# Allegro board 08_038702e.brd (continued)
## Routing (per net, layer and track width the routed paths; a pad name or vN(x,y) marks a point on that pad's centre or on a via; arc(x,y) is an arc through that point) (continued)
IO_L06_12_JX3_P: length 72.1
  TOP w0.089: U1.AA13 v1(26.22,31.59)
  L7_SIG w0.089: v1(15.5,37.32) 15.55,37.32 15.88,37.66 16.83,37.66 17.03,37.46 17.03,37.01 17.07,36.97 17.07,34.62 17.15,34.54 17.15,34.04 17.43,33.76 18.45,33.76 18.72,34.04 18.72,35.72 18.8,35.8 18.8,36.29 18.72,36.38 18.72,37.63 18.74,37.65 18.74,38.14 18.72,38.15 18.72,38.52 18.8,38.6 18.8,39.09 18.72,39.17 18.72,40.03 19.06,40.37 19.53,40.37 19.86,40.03 19.86,38.56 19.95,38.47 19.95,38.2 19.86,38.11 19.86,36.63 19.78,36.55 19.78,36.06 19.86,35.98 19.86,34.62 19.95,34.54 19.95,34.26 19.86,34.18 19.86,31.95 19.95,31.87 19.95,27.29 20.33,26.91 21.06,26.91 21.08,26.93 21.28,26.93 21.35,27 21.46,27 21.81,27.34 21.81,33.79 22.02,34 22.35,34 22.62,33.73 22.62,33.34 22.66,33.31 22.66,32.87 22.62,32.83 22.62,32.34 22.66,32.31 22.66,31.87 22.62,31.83 22.62,27.29 22.99,26.93 23.35,26.93 23.37,26.91 24.06,26.91 24.08,26.93 24.52,26.93 24.88,27.29 24.88,27.73 25.08,27.93 25.35,27.93 25.36,27.92 26.07,27.92 26.08,27.93 26.35,27.93 26.48,27.8 26.6,27.68 26.6,25.25 26.93,24.92 28.42,24.92 28.88,25.38 28.88,27.73 28.88,27.73 28.88,28.3 28.88,28.3 28.88,28.81 28.5,29.19 28.37,29.19 28.31,29.25 28.08,29.25 27.88,29.45 27.88,30.32 27.48,30.72 26.85,30.72 26.6,30.46 26.6,29.57 26.55,29.53 26.55,29.45 26.35,29.25 26.27,29.25 26.21,29.19 25.26,29.19 25.2,29.25 25.08,29.25 24.88,29.45 24.88,31.73 25.08,31.93 25.52,31.93 25.56,31.96 25.84,31.96 v1(26.22,31.59)
  BOTTOM w0.089: v1(15.5,37.32) 15.33,37.48 14.56,37.48 14.28,37.2 14.28,36.77 13.95,36.43 13.51,36.43 13.26,36.17 JX3.64
IO_L06_13_JX2_N: length 72.2
  TOP w0.089: U1.AB24 v1(25.22,19.59)
  L3_SIG w0.089: v1(25.22,19.59) 25.55,19.92 25.71,19.92 25.82,19.81 25.82,19.55 25.59,19.32 25.59,19.02 25.62,18.98 25.62,17.34 26.1,16.87 27.59,16.87 27.88,17.16 27.88,20.66 27.81,20.73 27.81,20.83 27.46,21.18 27.36,21.18 27.35,21.19 26.14,21.19 25.88,21.45 25.88,28.87 26.01,29 26.42,29 26.55,28.87 26.55,22.33 26.93,21.95 27.5,21.95 27.88,22.33 27.88,22.8 28.08,23 28.35,23 28.55,22.8 28.55,19.51 28.63,19.43 28.63,18.84 28.62,18.83 28.62,15.22 29.01,14.84 36.37,14.84 37.01,14.21 38.15,14.21 38.53,13.82 38.53,12.55 38.03,12.05 38.03,9 38.53,8.49 38.82,8.49 38.9,8.41 39.39,8.41 39.47,8.49 40.97,8.49 41.07,8.39 41.07,7.45 40.84,7.22 38.96,7.22 38.66,6.92 38.66,6.5 38.96,6.2 40.99,6.2 41.22,5.97 41.22,5.66 41,5.44 39.44,5.44 38.68,4.68 38.26,4.68 38.03,4.91 38.03,7.52 38.15,7.65 v1(38.15,7.98)
  BOTTOM w0.089: JX2.20 38.33,7.3 38.03,7.6 38.03,7.86 v1(38.15,7.98)
IO_L06_13_JX2_P: length 72.2
  TOP w0.089: U1.AA24 v1(26.22,19.59)
  L3_SIG w0.089: v1(37.64,7.98) 37.64,7.65 37.57,7.58 37.57,7.47 37.77,7.27 37.77,4.81 38.15,4.43 38.79,4.43 39.55,5.19 41.11,5.19 41.48,5.56 41.48,6.08 41.09,6.46 39.06,6.46 38.91,6.61 38.91,6.82 39.06,6.97 40.95,6.97 41.33,7.35 41.33,8.49 41.07,8.74 39.36,8.74 39.28,8.66 39,8.66 38.92,8.74 38.64,8.74 38.28,9.1 38.28,11.94 38.79,12.45 38.79,13.93 38.26,14.46 37.11,14.46 36.48,15.09 29.11,15.09 28.88,15.33 28.88,18.73 28.88,18.73 28.88,19.54 28.81,19.61 28.81,22.91 28.46,23.25 27.97,23.25 27.62,22.91 27.62,22.44 27.39,22.21 27.04,22.21 26.81,22.44 26.81,28.97 26.53,29.25 25.9,29.25 25.62,28.97 25.62,21.34 26.03,20.94 27.24,20.94 27.26,20.93 27.35,20.93 27.55,20.73 27.55,20.63 27.62,20.56 27.62,17.27 27.48,17.13 26.2,17.13 25.88,17.45 25.88,19.09 25.84,19.13 25.84,19.22 25.84,19.22 26.13,19.5 v1(26.22,19.59)
  BOTTOM w0.089: v1(37.64,7.98) 37.81,7.82 37.81,7.6 37.53,7.32 JX2.18
IO_L06_33_JX1_N: length 73.2
  TOP w0.089: U1.E3 v1(43.22,41.59)
  L7_SIG w0.089: v1(43.22,41.59) 42.85,41.95 42.85,42.7 43.08,42.92 46.39,42.92 46.81,43.34 46.81,43.65 47.2,44.05 47.91,44.05 49.46,45.6 49.46,46.02 49.65,46.21 49.93,46.21 49.94,46.21 50.45,46.21 50.45,46.21 50.73,46.21 50.74,46.21 51.25,46.21 51.25,46.21 51.88,46.21 51.96,46.29 52.24,46.29 52.32,46.21 55.25,46.21 55.25,46.21 55.53,46.21 55.54,46.21 56.05,46.21 56.05,46.21 56.33,46.21 56.34,46.21 58.09,46.21 58.47,45.83 59.72,45.83 60.6,46.72 64.04,46.72 64.44,47.12 64.44,52.15 64.33,52.27 64.33,52.7 64.31,52.72 64.31,52.94 64.95,53.58 64.95,54.82 64.42,55.35 61.63,55.35 61.39,55.59 61.39,59.69 61.63,59.93 65.73,59.93 65.97,59.69 65.97,59.31 66.49,58.78 68.23,58.78 68.76,59.31 68.76,60.81 68.38,61.2 60.38,61.2 60,60.81 60,56.12 59.62,55.73 55.91,55.73 55.68,55.97 55.68,56.62 v1(55.93,56.88)
  BOTTOM w0.089: v1(55.93,56.88) 55.64,56.59 55.64,56.5 55.93,56.21 JX1.63
IO_L06_33_JX1_P: length 73.2
  TOP w0.089: U1.F3 v1(42.22,41.59)
  L7_SIG w0.089: v1(42.22,41.59) 42.6,41.97 42.6,42.81 42.97,43.18 46.28,43.18 46.55,43.45 46.55,43.76 47.1,44.3 47.8,44.3 49.2,45.7 49.2,46.12 49.54,46.46 49.55,46.47 50.04,46.47 50.04,46.46 50.34,46.46 50.35,46.47 50.84,46.47 50.84,46.46 51.14,46.46 51.15,46.47 51.78,46.47 51.85,46.55 52.34,46.55 52.42,46.46 55.14,46.46 55.15,46.47 55.64,46.47 55.64,46.46 55.94,46.46 55.95,46.47 56.44,46.47 56.44,46.46 58.2,46.46 58.58,46.08 59.61,46.08 60.5,46.97 63.93,46.97 64.19,47.23 64.19,52.05 64.07,52.16 64.07,52.6 64.06,52.61 64.06,53.05 64.7,53.68 64.7,54.72 64.31,55.1 61.52,55.1 61.14,55.48 61.14,59.8 61.52,60.18 65.84,60.18 66.22,59.8 66.22,59.42 66.6,59.04 68.12,59.04 68.51,59.42 68.51,60.71 68.27,60.94 60.48,60.94 60.25,60.71 60.25,56.01 59.72,55.48 55.81,55.48 55.42,55.86 55.42,56.62 v1(55.17,56.88)
  BOTTOM w0.089: JX1.61 55.13,56.2 55.42,56.5 55.42,56.62 v1(55.17,56.88)
IO_L06_34_JX4_N: length 73.1
  TOP w0.089: U1.H8 v1(40.22,36.59)
  L4_SIG w0.089: v1(80.19,37.88) 80.52,38.21 80.95,38.21 81.08,38.08 81.08,37.57 81.21,37.45 81.33,37.45 81.46,37.57 81.46,38.08 81.59,38.21 81.84,38.21 81.97,38.08 81.97,37.95 82.03,37.89 82.16,37.89 82.22,37.95 82.22,38.08 82.35,38.21 82.5,38.21 83.51,37.19 84.22,37.19 84.24,37.21 84.52,37.21 84.54,37.19 86.9,37.19 87.43,37.72 87.43,37.85 87.66,38.08 89.23,38.08 89.33,37.98 89.33,37.23 89.26,37.16 89.26,36.61 89.33,36.54 89.33,35.27 89.23,35.16 81.97,35.16 81.44,34.63 81.44,33.89 81.06,33.51 70.43,33.51 70.11,33.19 69.87,33.19 69.68,33 69.51,33 69.32,33.19 69.07,33.19 68.88,33 68.71,33 68.52,33.19 68.27,33.19 68.08,33 67.91,33 67.52,33.39 67.47,33.39 67.1,33.77 67.1,33.82 65.62,35.3 65.62,35.84 65.28,36.17 64.74,36.17 64.74,36.18 63.93,36.18 63.68,36.43 61.63,36.43 60.83,37.23 60.67,37.23 60.62,37.27 60.13,37.27 60.09,37.23 59.22,37.23 58.93,36.94 56.46,36.94 56.33,36.81 54.28,36.81 52.25,34.78 51.77,34.78 51.53,35.01 49.65,35.01 49.33,34.69 48.78,34.69 48.29,35.18 40.04,35.18 39.84,35.38 39.84,36.22 v1(40.22,36.59)
  BOTTOM w0.089: JX4.34 80.88,37.77 80.57,38.08 80.44,38.08 80.24,37.88 v1(80.19,37.88)
IO_L06_34_JX4_P: length 73.1
  TOP w0.089: U1.J8 v1(39.22,36.59)
  L4_SIG w0.089: v1(39.22,36.59) 39.59,36.22 39.59,35.27 39.93,34.92 48.19,34.92 48.68,34.44 49.33,34.44 49.42,34.34 51.58,34.34 51.77,34.53 52.35,34.53 54.38,36.55 56.44,36.55 56.57,36.68 59.03,36.68 59.32,36.98 60.19,36.98 60.24,37.02 60.52,37.02 60.56,36.98 60.72,36.98 61.52,36.18 63.57,36.18 63.83,35.92 64.63,35.92 64.64,35.92 65.18,35.92 65.36,35.73 65.36,35.19 65.7,34.85 65.7,34.37 66.08,33.99 66.12,33.99 66.3,33.82 66.3,33.77 66.88,33.19 66.92,33.19 67.1,33.02 67.1,32.97 67.47,32.59 67.72,32.59 67.87,32.75 68.12,32.75 68.27,32.59 68.52,32.59 68.67,32.75 68.92,32.75 69.07,32.59 69.32,32.59 69.47,32.75 69.72,32.75 69.87,32.59 70.12,32.59 70.3,32.77 70.3,33.01 70.54,33.26 81.17,33.26 81.7,33.78 81.7,34.53 82.08,34.91 89.33,34.91 89.59,35.16 89.59,36.65 89.51,36.72 89.51,37.05 89.59,37.12 89.59,38.08 89.33,38.34 87.56,38.34 87.17,37.95 87.17,37.83 86.79,37.45 84.64,37.45 84.63,37.47 84.14,37.47 84.12,37.45 83.62,37.45 82.6,38.46 v1(80.19,38.46)
  BOTTOM w0.089: JX4.32 80.81,38.57 80.57,38.34 80.32,38.34 v1(80.19,38.46)
IO_L06_35_RX_D5_N: length 39.4
  TOP w0.089: U1.E13 v1(43.22,31.59) ; v6(64.4,32.09) U17.J7
  L15_SIG w0.089: v1(43.22,31.59) 43.2,31.6 42.9,31.6 42.81,31.7 42.81,31.82 42.91,31.92 47.36,31.92 47.44,32 47.46,32 47.81,32.34 47.81,34.11 47.84,34.14 48.71,34.14 48.82,34.04 48.82,32.13 49.22,31.73 49.46,31.73 49.47,31.72 51.14,31.72 51.29,31.57 51.29,29.9 52.13,29.05 53.04,29.05 53.25,28.84 53.25,26.29 54.1,25.45 54.13,25.45 54.14,25.46 54.42,25.46 54.46,25.43 55.91,25.43 55.95,25.39 56.44,25.39 56.78,25.73 56.78,25.78 57.13,26.12 57.24,26.12 57.26,26.14 57.69,26.14 58.09,26.55 58.09,27.18 58.2,27.29 58.62,27.29 58.73,27.18 58.73,26.55 59.13,26.14 59.62,26.14 59.87,26.4 59.87,28.96 60.61,29.7 63.04,29.7 63.54,30.2 63.72,30.2 63.89,30.37 63.89,30.55 64.4,31.05 v6(64.4,32.09)
IO_L06_35_RX_D5_P: length 39.4
  TOP w0.089: v6(63.6,31.29) U17.H8 ; U1.F13 v1(42.22,31.59)
  L15_SIG w0.089: v1(42.22,31.59) 42.81,32.18 47.26,32.18 47.33,32.25 47.35,32.25 47.55,32.45 47.55,34.21 47.74,34.4 48.82,34.4 49.07,34.14 49.07,32.24 49.33,31.99 49.56,31.99 49.57,31.97 51.24,31.97 51.54,31.68 51.54,30.01 52.24,29.31 53.15,29.31 53.51,28.95 53.51,26.4 54.19,25.72 54.53,25.72 54.56,25.68 56.02,25.68 56.05,25.64 56.33,25.64 56.53,25.84 56.53,25.88 57.03,26.38 57.13,26.38 57.15,26.4 57.58,26.4 57.84,26.65 57.84,27.29 58.09,27.54 58.73,27.54 58.98,27.29 58.98,26.65 59.23,26.4 59.51,26.4 59.62,26.5 59.62,29.06 60.5,29.95 62.94,29.95 63.3,30.31 63.3,30.59 63.3,30.59 63.3,30.62 63.47,30.79 63.76,30.79 64.14,31.18 64.14,31.52 64.06,31.6 63.81,31.6 63.68,31.48 63.68,31.38 v6(63.6,31.29)
IO_L07_12_JX3_N: length 72.6
  TOP w0.089: U1.AD10 v1(23.22,34.59)
  L7_SIG w0.089: v1(23.22,34.59) 22.84,34.96 22.84,41.62 22.81,41.65 22.81,41.83 22.46,42.18 21.97,42.18 21.94,42.15 21.49,42.15 21.46,42.18 20.97,42.18 20.94,42.15 19.84,42.15 19.61,42.38 19.61,42.8 19.84,43.03 20.93,43.03 20.97,43 21.46,43 21.5,43.03 21.93,43.03 21.97,43 22.46,43 22.81,43.34 22.81,43.53 22.84,43.56 22.84,44.12 22.53,44.43 19.86,44.43 19.48,44.81 19.48,48.68 19.82,49.01 19.82,49.5 19.47,49.85 19.47,50.8 19.71,51.04 20.32,51.04 20.57,51.29 21.1,51.29 21.12,51.27 21.66,51.27 21.68,51.29 24.06,51.29 24.44,51.67 24.44,52.56 24.06,52.94 23.29,52.94 22.91,53.32 22.91,53.83 22.53,54.21 22.06,54.21 21.66,54.61 21.12,54.61 20.72,54.21 18.24,54.21 17.73,53.7 16.69,53.7 16.31,54.08 16.31,55.2 15.78,55.73 14.81,55.73 14.28,55.2 14.28,52.69 14.66,52.31 17.62,52.31 17.85,52.07 17.85,43.03 17.47,42.65 16.3,42.65 16.02,42.38 15.94,42.38 15.57,42.02 14.91,42.02 14.78,42.15 v3(14.53,42.15)
  L17_SIG w0.089: v3(14.53,42.15) 14.52,42.14 14.39,42.14 14.25,42.27 13.41,42.27 11.74,40.6 10.55,40.6 10.32,40.84 10.19,40.84 10.03,41 v3(9.83,41)
  L19_GND w0.089: v3(9.83,41) 9.7,40.88 v4(9.45,40.88)
  BOTTOM w0.089: v4(9.45,40.88) 9.3,40.73 9.18,40.73 8.94,40.97 JX3.75
IO_L07_12_JX3_P: length 72.5
  TOP w0.089: U1.AE10 v1(22.22,34.59)
  L7_SIG w0.089: v1(22.22,34.59) 22.59,34.96 22.59,41.51 22.55,41.55 22.55,41.73 22.35,41.92 22.08,41.92 22.04,41.89 21.39,41.89 21.35,41.92 21.08,41.92 21.04,41.89 19.74,41.89 19.36,42.27 19.36,42.91 19.74,43.29 21.04,43.29 21.08,43.25 21.35,43.25 21.39,43.29 22.04,43.29 22.08,43.25 22.35,43.25 22.55,43.45 22.55,43.63 22.59,43.67 22.59,44.02 22.43,44.18 19.76,44.18 19.23,44.71 19.23,48.78 19.57,49.12 19.57,49.4 19.37,49.59 19.3,49.59 19.21,49.68 19.21,49.84 19.22,49.85 19.22,50.91 19.6,51.29 20.22,51.29 20.47,51.54 21.2,51.54 21.22,51.52 21.55,51.52 21.57,51.54 23.95,51.54 24.18,51.78 24.18,52.45 23.95,52.69 23.19,52.69 22.66,53.22 22.66,53.72 22.43,53.96 21.95,53.96 21.55,54.36 21.22,54.36 20.82,53.96 18.34,53.96 17.83,53.45 16.58,53.45 16.05,53.98 16.05,55.1 15.67,55.48 14.91,55.48 14.53,55.1 14.53,52.79 14.76,52.56 17.73,52.56 18.11,52.18 18.11,42.93 17.58,42.4 16.4,42.4 16.13,42.13 16.04,42.13 15.8,41.88 15.8,41.64 15.67,41.51 15.55,41.51 15.29,41.76 15.17,41.76 15.09,41.69 v3(14.78,41.69)
  L17_SIG w0.089: v3(14.78,41.69) 14.48,41.69 14.15,42.02 13.51,42.02 11.84,40.35 10.45,40.35 10.26,40.54 10,40.54 v3(9.83,40.37)
  L19_GND w0.089: v4(9.45,40.37) v3(9.83,40.37)
  BOTTOM w0.089: JX3.73 8.87,40.17 9.2,40.49 9.32,40.49 v4(9.45,40.37)
IO_L07_13_JX2_N: length 74
  TOP w0.089: U1.AF22 v1(21.22,21.59)
  L7_SIG w0.089: v1(40.57,12.43) 40.57,13.82 40.69,13.95 41.51,13.95 41.85,13.61 41.85,13.28 41.84,13.26 41.84,12.4 41.86,12.37 41.86,12.09 41.2,11.42 41.2,9.2 41.12,9.12 41.12,8.63 41.2,8.54 41.2,8.26 41.73,7.73 45.77,7.73 46.15,7.35 46.15,5.44 46.53,5.06 47.15,5.06 47.68,5.59 47.68,7.16 47.86,7.35 48.13,7.35 48.31,7.16 48.31,5.59 48.84,5.06 49.84,5.06 50.22,5.44 50.22,6.71 50.98,7.47 50.98,9.87 50.45,10.4 44.73,10.4 44.5,10.63 44.5,12.88 43.01,14.37 42.49,14.37 41.89,14.97 39.19,14.97 38.17,13.95 37.75,13.95 37.37,14.33 31.65,14.33 30.89,15.09 26.19,15.09 25.81,15.48 25.81,22.83 25.46,23.18 21.97,23.18 21.62,22.83 21.62,22.45 21.59,22.41 21.59,21.96 v1(21.22,21.59)
  BOTTOM w0.089: JX2.25 40.73,11.72 40.4,12.05 40.4,12.26 v1(40.57,12.43)
IO_L07_13_JX2_P: length 74
  TOP w0.089: U1.AE22 v1(22.22,21.59)
  L7_SIG w0.089: v1(39.93,12.43) 39.8,12.55 39.68,12.55 39.55,12.68 39.55,12.81 39.68,12.94 40.18,12.94 40.31,13.06 40.31,13.93 40.59,14.21 40.8,14.21 41.62,14.21 42.11,13.71 42.11,13.17 42.09,13.15 42.09,12.5 42.12,12.47 42.12,11.98 41.45,11.32 41.45,9.09 41.37,9.01 41.37,8.73 41.45,8.65 41.45,8.36 41.84,7.98 45.88,7.98 46.41,7.45 46.41,5.55 46.64,5.32 47.04,5.32 47.42,5.7 47.42,7.27 47.76,7.6 48.23,7.6 48.57,7.27 48.57,5.7 48.95,5.32 49.73,5.32 49.96,5.55 49.96,6.82 50.73,7.58 50.73,9.76 50.34,10.14 44.63,10.14 44.25,10.52 44.25,12.77 42.91,14.11 42.38,14.11 41.78,14.71 39.3,14.71 38.28,13.7 37.64,13.7 37.26,14.08 31.55,14.08 30.79,14.84 26.09,14.84 25.55,15.38 25.55,22.73 25.35,22.93 22.08,22.93 21.88,22.73 21.88,22.36 21.84,22.31 21.84,21.96 v1(22.22,21.59)
  BOTTOM w0.089: JX2.23 39.93,11.79 40.18,12.05 40.18,12.17 v1(39.93,12.43)
IO_L07_33_JX1_N: length 72.7
  TOP w0.089: U1.H1 v1(40.22,43.59)
  L14_SIG w0.089: v1(55.81,49.51) 55.68,49.38 55.68,48.47 56.04,48.11 61.8,48.11 62.05,48.37 62.05,48.88 62.3,49.13 63.28,49.13 64.04,48.37 64.46,48.37 65.22,49.13 72.06,49.13 72.44,49.51 73.46,49.51 73.84,49.13 73.84,48.51 73.46,48.13 72.7,48.13 72.04,47.48 71.48,47.48 71.47,47.5 71.13,47.5 71.11,47.48 65.33,47.48 65.08,47.23 65.08,47.07 64.99,46.98 64.99,46.76 64.82,46.59 63.04,46.59 62.66,46.21 62.66,45.57 62.62,45.53 62.62,45.46 62.27,45.11 61.78,45.11 61.7,45.19 61.65,45.19 61.27,45.57 61.27,46.21 60.89,46.59 59.62,46.59 59.23,46.21 59.23,45.45 58.85,45.07 58.09,45.07 57.71,45.45 57.71,46.21 57.33,46.59 55.55,46.59 54.79,47.35 54.79,48.39 54.54,48.64 54.54,49.74 55.06,50.27 55.45,50.27 55.68,50.51 55.68,50.68 55.45,50.91 48.04,50.91 47.1,49.98 47.03,49.98 46.83,49.78 46.83,49.7 44.65,47.52 44.65,47.46 44.27,47.08 44.21,47.08 43.21,46.08 41.05,46.08 40.44,45.47 40.44,44.83 39.84,44.24 39.84,43.96 v1(40.22,43.59)
  BOTTOM w0.089: JX1.64 55.93,50.31 55.64,50.02 55.64,49.68 v1(55.81,49.51)
IO_L07_33_JX1_P: length 72.7
  TOP w0.089: U1.J1 v1(39.22,43.59)
  L14_SIG w0.089: v1(55.26,49.48) 55.42,49.32 55.42,48.37 55.93,47.86 61.9,47.86 62.3,48.26 62.3,48.77 62.41,48.88 63.17,48.88 63.93,48.11 64.57,48.11 65.33,48.88 72.17,48.88 72.55,49.26 73.35,49.26 73.59,49.03 73.59,48.62 73.35,48.39 72.59,48.39 71.94,47.73 71.59,47.73 71.57,47.75 71.03,47.75 71.01,47.73 65.22,47.73 64.82,47.33 64.82,47.17 64.74,47.09 64.74,46.87 64.72,46.84 62.94,46.84 62.41,46.31 62.41,45.68 62.36,45.63 62.36,45.56 62.17,45.37 61.89,45.37 61.81,45.45 61.75,45.45 61.52,45.68 61.52,46.31 60.99,46.84 59.51,46.84 58.98,46.31 58.98,45.55 58.75,45.32 58.2,45.32 57.96,45.55 57.96,46.31 57.43,46.84 55.66,46.84 55.04,47.46 55.04,48.5 54.79,48.75 54.79,49.64 55.17,50.02 55.55,50.02 55.93,50.4 55.93,50.78 55.55,51.16 47.93,51.16 47,50.23 46.92,50.23 46.58,49.88 46.58,49.81 44.39,47.63 44.39,47.57 44.16,47.33 44.1,47.33 43.11,46.34 40.95,46.34 40.18,45.57 40.18,44.94 39.59,44.34 39.59,43.96 v1(39.22,43.59)
  BOTTOM w0.089: JX1.62 55.13,50.22 55.39,49.96 55.39,49.62 v1(55.26,49.48)
IO_L07_34_JX4_N: length 72.4
  TOP w0.089: U1.E5 v1(43.22,39.59)
  L17_SIG w0.089: v1(84.38,36.24) 84.32,36.24 84.19,36.11 84.06,36.11 83.87,36.3 83.87,36.35 83.95,36.43 83.95,36.56 83.88,36.62 83.47,36.62 81.17,38.93 78.45,38.93 73.33,44.05 73.33,49.64 72.7,50.27 71.17,50.27 70.79,49.89 70.79,47.48 70.41,47.1 68.63,47.1 68.25,47.48 68.25,49.89 67.87,50.27 65.33,50.27 63.25,48.2 59.96,48.2 59.96,48.19 59.47,48.19 59.46,48.2 55.76,48.2 54.79,47.23 54.79,44.81 54.41,44.43 53.14,44.43 52.76,44.81 52.76,47.82 52.38,48.2 51.63,48.2 49.46,46.02 49.46,45.76 47.88,44.18 43.11,44.18 42.85,43.92 42.85,40.06 42.84,40.05 42.84,39.96 v1(43.22,39.59)
  BOTTOM w0.089: v1(84.38,36.24) 84.55,36.41 84.76,36.41 85,36.17 JX4.37
IO_L07_34_JX4_P: length 72.4
  TOP w0.089: U1.F5 v1(42.22,39.59)
  L17_SIG w0.089: v1(84.38,36.88) 83.58,36.88 81.27,39.18 78.56,39.18 73.59,44.16 73.59,49.74 72.8,50.53 71.07,50.53 70.54,50 70.54,47.58 70.3,47.35 68.74,47.35 68.51,47.58 68.51,50 67.98,50.53 65.22,50.53 63.15,48.45 59.86,48.45 59.85,48.44 59.57,48.44 59.57,48.45 55.66,48.45 54.54,47.33 54.54,44.92 54.3,44.69 53.24,44.69 53.01,44.92 53.01,47.92 52.48,48.45 51.53,48.45 49.2,46.12 49.2,45.86 47.77,44.43 43,44.43 42.6,44.03 42.6,40.17 42.59,40.16 42.59,39.96 v1(42.22,39.59)
  BOTTOM w0.089: v1(84.38,36.88) 84.63,36.62 84.76,36.62 85.11,36.97 JX4.35
IO_L07_35_RX_FRAME_N: length 35.9
  TOP w0.089: U1.H12 v1(40.22,32.59) ; v6(64.4,30.49) U17.G7
  L17_SIG w0.089: v6(64.4,30.49) 64.18,30.49 64.13,30.54 64.13,30.76 64.05,30.84 63.89,31 63.47,31 63.3,31.17 63.3,31.5 63,31.79 62.59,31.79 62.3,31.5 62.3,31.17 62.12,30.99 60.23,30.99 59.58,31.64 58.49,31.64 58.05,32.09 54.44,32.09 54.42,32.07 53.93,32.07 53.69,31.83 53.69,31.48 53.57,31.35 52.61,31.35 52.53,31.43 52.53,32.37 52.27,32.62 51.79,32.62 51.39,32.22 51.39,31.58 51.28,31.48 50.83,31.48 50.73,31.58 50.73,32.37 50.47,32.62 49.88,32.62 49.48,32.22 49.48,31.51 49.4,31.43 49.32,31.43 49.32,31.43 49.2,31.43 48.95,31.69 48.95,32.22 48.54,32.62 47.83,32.62 47.58,32.37 47.58,31.48 47.55,31.45 47.55,31.3 47.5,31.25 47.35,31.25 47.32,31.22 46.89,31.22 46.81,31.31 46.81,31.83 46.46,32.18 46.42,32.18 46.39,32.22 45.03,32.22 45,32.18 44.97,32.18 44.63,31.83 44.63,31.32 44.52,31.22 43.85,31.22 43.81,31.26 43.81,31.83 43.46,32.18 43.37,32.18 43.34,32.22 40.59,32.22 v1(40.22,32.59)
IO_L07_35_RX_FRAME_P: length 36.1
  TOP w0.089: U1.H13 v1(40.22,31.59) ; v6(63.6,30.49) U17.G8
  L17_SIG w0.089: v1(40.22,31.59) 40.59,31.96 43.23,31.96 43.27,31.92 43.35,31.92 43.55,31.73 43.55,31.16 43.74,30.97 44.63,30.97 44.88,31.22 44.88,31.73 45.08,31.92 45.1,31.92 45.14,31.96 46.28,31.96 46.32,31.92 46.35,31.92 46.55,31.73 46.55,31.21 46.79,30.97 47.43,30.97 47.46,31 47.6,31 47.81,31.2 47.81,31.35 47.83,31.37 47.83,32.26 47.94,32.37 48.44,32.37 48.69,32.11 48.69,31.58 49.1,31.18 49.21,31.18 49.22,31.18 49.59,31.18 49.73,31.33 49.73,32.11 49.99,32.37 50.37,32.37 50.47,32.26 50.47,31.48 50.73,31.22 51.39,31.22 51.64,31.48 51.64,32.11 51.89,32.37 52.17,32.37 52.27,32.26 52.27,31.33 52.5,31.1 53.67,31.1 53.95,31.37 53.95,31.8 54.01,31.87 54.51,31.87 54.52,31.88 57.96,31.88 58.41,31.44 59.49,31.44 60.14,30.79 62.2,30.79 62.5,31.09 62.5,31.42 62.67,31.59 62.92,31.59 63.1,31.42 63.1,31.09 63.39,30.79 63.45,30.79 63.45,30.79 63.74,30.79 63.87,30.66 63.87,30.44 63.93,30.36 63.93,30.28 63.86,30.23 63.76,30.23 63.68,30.31 63.68,30.41 v6(63.6,30.49)
IO_L08_12_JX3_N: length 72.8
  TOP w0.089: U1.AF12 v1(21.22,32.59)
  L15_SIG w0.089: v3(14.02,41) 13.28,41 12.75,40.47 12.75,38.44 12.52,38.21 8.96,38.21 8.43,37.68 8.43,37.04 8.79,36.68 9.45,36.68 9.96,36.18 9.96,35.75 10.34,35.37 14.92,35.37 15.01,35.29 15.52,35.29 15.63,35.4 15.69,35.4 17.32,37.03 17.32,39.48 15.8,41 15.8,42.04 16.56,42.8 16.56,51.95 16.79,52.18 17.6,52.18 17.83,51.95 17.83,40.77 18.85,39.75 18.85,34.25 18.62,34.02 16.08,34.02 15.55,33.49 15.55,31.35 15.93,30.97 19.99,30.97 20.37,31.35 20.37,33.51 20.79,33.93 21.35,33.93 21.59,33.69 21.59,32.96 v1(21.22,32.59)
  L19_GND w0.089: v4(13.36,40.97) 13.99,40.97 v3(14.02,41)
  BOTTOM w0.089: JX3.76 v4(13.36,40.97)
IO_L08_12_JX3_P: length 72.8
  TOP w0.089: U1.AE12 v1(22.22,32.59)
  L15_SIG w0.089: v1(22.22,32.59) 21.84,32.96 21.84,33.8 21.46,34.18 20.68,34.18 20.12,33.61 20.12,31.46 19.89,31.22 16.03,31.22 15.8,31.46 15.8,33.38 16.18,33.76 18.72,33.76 19.1,34.14 19.1,39.86 18.09,40.88 18.09,52.05 17.71,52.43 16.69,52.43 16.31,52.05 16.31,42.91 15.55,42.15 15.55,40.9 17.07,39.37 17.07,37.13 15.59,35.65 15.53,35.65 15.42,35.54 15.11,35.54 15.03,35.62 10.44,35.62 10.21,35.86 10.21,36.28 9.56,36.94 8.9,36.94 8.69,37.15 8.69,37.57 9.07,37.95 12.63,37.95 13.01,38.34 13.01,40.37 13.39,40.75 13.46,40.75 13.54,40.67 13.67,40.67 13.74,40.75 13.8,40.75 13.88,40.67 13.89,40.67 13.9,40.66 13.9,40.49 13.95,40.44 v3(14.02,40.44)
  L19_GND w0.089: v4(13.39,40.24) 13.82,40.24 v3(14.02,40.44)
  BOTTOM w0.089: v4(13.39,40.24) 13.32,40.17 JX3.74
IO_L08_13_JX2_N: length 73.9
  TOP w0.089: U1.AF23 v1(21.22,20.59)
  L7_SIG w0.089: v1(21.22,20.59) 21.61,20.59 21.64,20.56 21.64,20.41 21.41,20.18 20.65,20.18 20.25,19.77 20.25,13.47 22.81,10.9 24.58,10.9 25.2,10.29 25.2,6.48 26.49,5.19 27.52,5.19 27.6,5.27 27.67,5.27 28.99,6.59 35.13,6.59 35.87,5.85 35.87,3.69 36.27,3.28 36.63,3.28 36.88,3.03 36.88,1.76 37.14,1.51 53.52,1.51 53.9,1.89 53.9,3.16 53.52,3.54 46,3.54 45.77,3.77 45.77,4.1 45.85,4.18 45.85,5.44 45.47,5.82 40.73,5.82 40.5,6.06 40.5,7.92 v1(40.57,7.98)
  BOTTOM w0.089: v1(40.57,7.98) 40.44,7.86 40.44,7.6 40.73,7.31 JX2.26
IO_L08_13_JX2_P: length 74
  TOP w0.089: U1.AE23 v1(22.22,20.59)
  L7_SIG w0.089: v1(22.22,20.59) 22.18,20.56 21.99,20.56 21.9,20.47 21.9,20.3 21.52,19.93 20.76,19.93 20.5,19.67 20.5,13.57 22.91,11.16 24.69,11.16 25.45,10.4 25.45,6.59 26.6,5.44 27.41,5.44 27.49,5.52 27.57,5.52 28.88,6.84 35.23,6.84 36.12,5.95 36.12,3.79 36.37,3.54 36.73,3.54 37.14,3.13 37.14,1.86 37.24,1.76 53.41,1.76 53.65,1.99 53.65,3.05 53.41,3.28 45.9,3.28 45.52,3.66 45.52,4.2 45.6,4.29 45.6,5.34 45.37,5.57 40.63,5.57 40.25,5.95 40.25,6.9 40.06,7.09 39.73,7.09 39.63,7.2 39.63,7.37 39.73,7.47 40.12,7.47 40.25,7.6 40.25,7.79 v1(40.06,7.98)
  BOTTOM w0.089: v1(40.06,7.98) 40.22,7.82 40.22,7.6 39.93,7.31 JX2.24
IO_L08_33_JX1_N: length 73.5
  TOP w0.089: U1.H3 v1(40.22,41.59)
  L15_SIG w0.089: v1(40.22,41.59) 40.55,41.25 43.5,41.25 43.61,41.36 43.61,44.07 43.36,44.33 43.36,45.55 43.76,45.96 47.19,45.96 47.53,46.3 47.53,47.24 47.91,47.63 49.64,47.63 50.16,47.1 50.34,47.1 51.87,48.62 55.4,48.62 55.78,48.24 64.59,48.24 64.82,48.47 64.82,49.91 64.59,50.15 55.45,50.15 54.92,50.68 54.92,51.27 55.19,51.54 65.48,51.54 65.71,51.78 65.71,52.45 65.48,52.69 65.04,52.69 64.89,52.83 64.56,52.83 64.42,52.69 62.86,52.69 62.48,52.31 61.03,52.31 60.53,52.81 56.33,52.81 55.81,53.34 55.81,54.74 56.17,55.1 57.39,55.1 57.84,54.65 57.84,54.3 57.93,54.21 57.97,54.21 v1(58.22,53.96)
  BOTTOM w0.089: v1(58.22,53.96) 58.22,54.09 58.07,54.23 58.07,54.36 58.33,54.61 JX1.69
IO_L08_33_JX1_P: length 73.4
  TOP w0.089: U1.H4 v1(40.22,40.59)
  L15_SIG w0.089: v1(40.22,40.59) 40.62,41 43.61,41 43.87,41.26 43.87,44.18 43.61,44.43 43.61,45.45 43.87,45.7 47.3,45.7 47.79,46.19 47.79,47.14 48.02,47.37 49.53,47.37 50.06,46.84 50.45,46.84 51.97,48.37 55.3,48.37 55.68,47.99 64.7,47.99 65.08,48.37 65.08,50.02 64.7,50.4 55.55,50.4 55.17,50.78 55.17,51.16 55.3,51.29 65.58,51.29 65.97,51.67 65.97,52.56 65.58,52.94 65.14,52.94 65,53.09 64.46,53.09 64.31,52.94 62.76,52.94 62.38,52.56 61.14,52.56 60.63,53.07 56.44,53.07 56.06,53.45 56.06,54.63 56.27,54.85 56.54,54.85 56.75,54.64 56.75,54.54 56.82,54.46 56.95,54.46 57.08,54.59 57.08,54.72 57.2,54.85 57.29,54.85 57.59,54.55 v1(57.59,53.96)
  BOTTOM w0.089: v1(57.59,53.96) 57.59,53.96 57.84,54.21 57.84,54.34 57.53,54.65 JX1.67
IO_L08_34_JX4_N: length 73.5
  TOP w0.089: U1.D8 v1(44.22,36.59)
  L4_SIG w0.089: v1(80.19,36.34) 80.17,36.36 80.17,36.54 80.23,36.6 80.33,36.6 80.41,36.68 80.83,36.68 80.94,36.58 80.94,36.43 80.82,36.31 80.7,36.31 80.57,36.18 80.57,35.92 80.7,35.8 80.82,35.8 80.94,35.68 80.94,35.41 80.81,35.29 79.81,35.29 79.68,35.41 79.68,38.08 79.3,38.46 78.67,38.46 78.28,38.08 78.28,34.5 78.05,34.27 77.25,34.27 77.01,34.5 77.01,37.55 76.48,38.08 75.36,38.08 74.98,37.7 74.98,34.63 74.75,34.4 74.2,34.4 73.97,34.63 73.97,37.55 73.44,38.08 72.34,38.08 71.81,37.55 71.81,34.5 71.57,34.27 70.9,34.27 70.66,34.5 70.66,37.55 70.13,38.08 69.67,38.08 69.14,37.55 69.14,34.88 68.91,34.65 68.48,34.65 68.25,34.88 68.25,37.55 67.72,38.08 66.44,38.08 66.19,37.83 66.19,37.57 65.93,37.32 63.43,37.32 63.3,37.45 62.66,37.45 62.54,37.32 61.65,37.32 61.01,37.95 57.71,37.95 57.33,38.34 54.68,38.34 54.04,37.69 53.41,37.69 52.61,36.9 52.61,36.66 52.38,36.43 51.84,36.43 51.58,36.68 49.6,36.68 49.35,36.43 47.95,36.43 47.7,36.18 44.97,36.18 44.97,36.18 44.63,36.18 v1(44.22,36.59)
  BOTTOM w0.089: JX4.38 80.83,36.17 80.47,36.53 80.38,36.53 v1(80.19,36.34)
IO_L08_34_JX4_P: length 73.5
  TOP w0.089: U1.D9 v1(44.22,35.59)
  L4_SIG w0.089: v1(80.19,36.94) 80.94,36.94 81.19,36.68 81.19,35.29 80.94,35.03 79.68,35.03 79.43,35.29 79.43,37.98 79.19,38.21 78.77,38.21 78.54,37.98 78.54,34.4 78.16,34.02 77.14,34.02 76.76,34.4 76.76,37.45 76.38,37.83 75.47,37.83 75.24,37.6 75.24,34.53 74.86,34.14 74.09,34.14 73.71,34.53 73.71,37.45 73.33,37.83 72.44,37.83 72.06,37.45 72.06,34.4 71.68,34.02 70.79,34.02 70.41,34.4 70.41,37.45 70.03,37.83 69.78,37.83 69.39,37.45 69.39,34.78 69.01,34.4 68.38,34.4 68,34.78 68,37.45 67.62,37.83 66.55,37.83 66.44,37.72 66.44,37.47 66.04,37.07 63.32,37.07 63.19,37.19 62.77,37.19 62.64,37.07 61.54,37.07 60.91,37.7 57.6,37.7 57.22,38.08 54.79,38.08 54.15,37.44 53.51,37.44 52.86,36.79 52.86,36.56 52.48,36.18 51.77,36.18 51.53,35.94 49.65,35.94 49.42,36.18 48.06,36.18 47.81,35.92 45.08,35.92 45.07,35.92 44.55,35.92 v1(44.22,35.59)
  BOTTOM w0.089: v1(80.19,36.94) 80.38,36.75 80.51,36.75 80.73,36.97 JX4.36
IO_L08_35_FB_CLK_N: length 39.2
  TOP w0.089: v6(62,30.49) U17.G10 ; U1.J13 v1(39.22,31.59)
  L17_SIG w0.089: v6(62,30.49) 62.28,30.21 62.28,29.95 62.16,29.83 60.12,29.83 59.74,29.45 58.2,29.45 57.74,29.9 57.11,29.9 56.8,30.21 56.23,30.21 55.92,30.51 55.43,30.51 55.21,30.29 54.61,30.29 54.53,30.38 53.72,30.38 53.55,30.21 34.96,30.21 34.72,30.44 34.72,31.75 34.96,31.99 37.39,31.99 37.64,31.73 37.64,30.86 37.92,30.59 38.49,30.59 38.84,30.94 38.84,31.32 38.7,31.46 38.57,31.59 38.57,31.79 38.74,31.96 39.12,31.96 39.22,31.86 39.22,31.59 v1(39.22,31.59)
IO_L08_35_FB_CLK_P: length 38
  TOP w0.089: U1.K13 v1(38.22,31.59) ; v6(62,28.89) U17.F10
  L17_SIG w0.089: v1(38.22,31.59) 38.59,31.22 38.59,31.05 38.39,30.84 38.03,30.84 37.9,30.97 37.9,31.84 37.5,32.24 34.85,32.24 34.47,31.86 34.47,30.33 34.85,29.95 53.66,29.95 53.83,30.12 54.42,30.12 54.51,30.04 55.32,30.04 55.54,30.26 55.82,30.26 56.12,29.95 56.69,29.95 57,29.65 57.64,29.65 58.09,29.19 59.85,29.19 60.23,29.57 61.77,29.57 62.03,29.32 62.03,28.92 v6(62,28.89)
IO_L09_12_JX3_N: length 72.7
  TOP w0.089: U1.AF10 v1(21.22,34.59)
  L17_SIG w0.089: v3(7.29,43.16) 7.55,42.91 8.16,42.91 8.56,42.5 8.56,39.88 7.93,39.25 7.93,26.38 8.41,25.89 9.2,25.89 9.45,26.14 9.45,27.16 9.96,27.67 11.33,27.67 11.86,28.2 11.86,37.19 12.24,37.57 13.9,37.57 14.28,37.19 14.28,34 14.38,33.89 16.92,33.89 17.32,33.49 17.32,31.07 17.71,30.69 17.71,26.42 17.18,25.89 16.03,25.89 15.8,25.66 15.8,24.47 16.03,24.24 17.18,24.24 17.71,23.71 17.71,23.21 18.08,22.84 18.6,22.84 18.98,23.21 18.98,29.8 20.12,30.95 20.12,32.67 20.88,33.43 20.88,33.73 21.08,33.93 21.37,33.93 21.5,34.05 21.5,34.13 21.64,34.27 21.64,34.4 21.52,34.53 21.28,34.53 v1(21.22,34.59)
  L19_GND w0.089: v4(6.66,43.16) v3(7.29,43.16)
  BOTTOM w0.089: v4(6.66,43.16) 6.78,43.03 7.04,43.03 7.37,43.37 JX3.81
IO_L09_12_JX3_P: length 72.7
  TOP w0.089: U1.AE11 v1(22.22,33.59)
  L17_SIG w0.089: v1(22.22,33.59) 21.87,33.94 21.74,33.94 21.74,33.94 21.68,33.87 21.55,33.75 21.55,33.45 21.35,33.25 21.06,33.25 20.37,32.57 20.37,30.84 19.23,29.7 19.23,23.11 18.71,22.59 17.97,22.59 17.45,23.11 17.45,23.6 17.07,23.98 15.93,23.98 15.55,24.37 15.55,25.76 15.93,26.14 17.07,26.14 17.45,26.52 17.45,30.59 17.07,30.97 17.07,33.38 16.82,33.64 14.28,33.64 14.02,33.89 14.02,37.09 13.79,37.32 12.35,37.32 12.12,37.09 12.12,28.09 11.44,27.41 10.06,27.41 9.7,27.05 9.7,26.04 9.3,25.64 8.31,25.64 7.67,26.27 7.67,39.35 8.31,39.99 8.31,42.4 8.05,42.65 7.42,42.65 v3(7.29,42.53)
  L19_GND w0.089: v3(7.29,42.53) 7.29,42.56 7.2,42.65 v4(6.66,42.65)
  BOTTOM w0.089: JX3.79 7.28,42.57 7.04,42.82 6.82,42.82 v4(6.66,42.65)
IO_L09_13_JX2_N: length 72.2
  TOP w0.089: U1.AB22 v1(25.22,21.59)
  L4_SIG w0.089: v1(25.22,21.59) 25.59,21.96 26.46,21.96 26.6,21.83 26.6,16.26 27,15.86 28.14,15.86 28.25,15.75 28.25,14.74 28.65,14.33 29.24,14.33 29.64,14.74 29.64,15.5 29.75,15.6 30.41,15.6 30.66,15.86 30.66,17 30.88,17.22 30.88,26.73 31.08,26.92 33.35,26.92 33.55,26.73 33.55,26.7 33.6,26.65 33.6,24.33 33.81,24.13 33.81,22.08 33.96,21.93 33.96,19.89 33.71,19.64 33.71,18.64 34.47,17.88 34.47,13.7 34.85,13.32 35.1,13.32 35.49,12.94 35.49,12.55 36.56,11.48 36.58,11.48 36.65,11.41 37.26,11.41 37.64,11.03 37.64,10.27 37.9,10.01 43.77,10.01 43.79,10.03 46.66,10.03 46.92,10.28 46.92,10.65 46.66,10.9 38.89,10.9 38.79,11.01 38.79,11.31 38.89,11.41 42.45,11.41 42.89,11.85 42.89,12.21 v1(43.11,12.43)
  BOTTOM w0.089: v1(43.11,12.43) 42.83,12.15 42.83,12.03 43.13,11.73 JX2.31
IO_L09_13_JX2_P: length 72.3
  TOP w0.089: U1.AB21 v1(25.22,22.59)
  L4_SIG w0.089: v1(25.22,22.59) 25.07,22.44 25.07,22.21 25.21,22.07 25.34,22.07 25.48,22.22 26.56,22.22 26.85,21.93 26.85,16.36 27.1,16.11 28.25,16.11 28.5,15.86 28.5,14.84 28.75,14.59 29.14,14.59 29.39,14.84 29.39,15.6 29.64,15.86 30.3,15.86 30.41,15.96 30.41,17.1 30.63,17.32 30.63,26.83 30.97,27.18 33.46,27.18 33.81,26.83 33.81,26.8 33.85,26.76 33.85,24.44 34.06,24.23 34.06,22.19 34.22,22.03 34.22,19.79 33.96,19.53 33.96,18.75 34.72,17.99 34.72,13.8 34.96,13.57 35.21,13.57 35.74,13.04 35.74,12.66 36.66,11.73 36.69,11.73 36.76,11.67 37.37,11.67 37.9,11.14 37.9,10.37 38,10.27 43.67,10.27 43.68,10.28 46.56,10.28 46.66,10.39 46.66,10.54 46.56,10.65 38.79,10.65 38.53,10.9 38.53,11.41 38.79,11.67 42.34,11.67 42.64,11.96 42.64,12.28 42.62,12.3 42.6,12.3 v1(42.47,12.43)
  BOTTOM w0.089: v1(42.47,12.43) 42.6,12.3 42.6,12.05 42.33,11.78 JX2.29
IO_L09_33_JX1_N: length 72.1
  TOP w0.089: U1.K1 v1(38.22,43.59)
  L14_SIG w0.089: v1(58.22,49) 57.91,49.31 57.91,49.38 58.09,49.56 58.09,49.64 57.91,49.82 57.91,49.84 58.35,50.27 76.1,50.27 77.07,51.24 78.03,51.24 78.28,51.49 78.28,52.31 78.03,52.56 76.02,52.56 75.38,51.92 61.77,51.92 61.39,52.31 61.39,52.56 61.01,52.94 59.62,52.94 59.23,52.56 59.23,52.31 58.85,51.92 46.03,51.92 42.49,48.39 42.2,48.39 41.82,48 41.82,47.71 41.33,47.23 40.18,47.23 38.53,45.57 38.53,43.91 v1(38.22,43.59)
  BOTTOM w0.089: v1(58.22,49) 58.03,49.19 58.03,49.96 58.33,50.26 JX1.70
IO_L09_33_JX1_P: length 72.1
  TOP w0.089: U1.K2 v1(38.22,42.59)
  L14_SIG w0.089: v1(57.66,48.96) 57.66,49.95 58.24,50.53 76,50.53 76.96,51.49 77.92,51.49 78.03,51.6 78.03,52.2 77.92,52.31 76.13,52.31 75.49,51.67 61.67,51.67 61.14,52.2 61.14,52.45 60.91,52.69 59.72,52.69 59.49,52.45 59.49,52.2 58.96,51.67 46.13,51.67 42.59,48.13 42.3,48.13 42.07,47.9 42.07,47.61 41.43,46.97 40.29,46.97 38.79,45.47 38.79,43.16 v1(38.22,42.59)
  BOTTOM w0.089: v1(57.66,48.96) 57.75,49.05 57.75,49.08 57.81,49.14 57.81,49.96 57.53,50.24 JX1.68
IO_L09_34_JX4_N: length 72.3
  TOP w0.089: U1.E8 v1(43.22,36.59)
  L17_SIG w0.089: v1(84.38,33.89) 84.19,34.08 84.19,34.18 84.1,34.27 83.87,34.27 83.75,34.14 83.75,34.01 83.63,33.89 83.36,33.89 83.24,34.02 83.24,34.14 83.11,34.27 82.69,34.27 81.21,35.75 79.94,35.75 79.39,36.3 77.42,36.3 71.96,41.76 67.38,41.76 66.85,42.29 66.85,43.9 67.38,44.43 70.56,44.43 70.79,44.66 70.79,45.34 70.56,45.57 67.38,45.57 66.85,46.1 66.85,46.99 66.62,47.23 64.01,47.23 63.68,46.9 63.68,45.34 63.15,44.81 61.5,44.81 61.27,44.58 61.27,43.25 61.27,43.25 61.27,43.03 61.26,43.03 61.26,42.88 60.91,42.53 60.89,42.53 60.88,42.52 59.11,42.52 58.97,42.65 56.89,42.65 56.78,42.54 54.47,42.54 53.72,43.29 52.73,43.29 52.52,43.08 49.59,43.08 49.38,43.29 47.75,43.29 47.46,43 44.15,43 43.88,42.73 43.88,39.34 43.46,38.92 42.08,38.92 41.99,38.84 41.91,38.84 41.82,38.75 41.82,37.19 42.08,36.92 42.35,36.92 42.72,36.56 43.18,36.56 v1(43.22,36.59)
  BOTTOM w0.089: v1(84.38,33.89) 84.55,34.06 84.89,34.06 85.17,33.77 JX4.43
IO_L09_34_JX4_P: length 72.4
  TOP w0.089: U1.F9 v1(42.22,35.59)
  L17_SIG w0.089: v1(84.38,34.53) 82.79,34.53 81.31,36 80.05,36 79.5,36.56 77.52,36.56 72.06,42.02 67.49,42.02 67.11,42.4 67.11,43.8 67.49,44.18 70.66,44.18 71.05,44.56 71.05,45.45 70.66,45.83 67.49,45.83 67.11,46.21 67.11,47.1 66.73,47.48 63.9,47.48 63.43,47 63.43,45.45 63.04,45.07 61.39,45.07 61.01,44.69 61.01,43.14 61.01,43.13 61.01,42.98 60.81,42.79 60.79,42.79 60.77,42.77 59.21,42.77 59.08,42.91 56.79,42.91 56.68,42.8 54.57,42.8 53.83,43.54 52.73,43.54 52.45,43.81 49.65,43.81 49.38,43.54 47.65,43.54 47.35,43.25 44.04,43.25 43.62,42.83 43.62,39.45 43.35,39.18 41.97,39.18 41.89,39.1 41.8,39.1 41.56,38.86 41.56,37.08 41.84,36.81 41.84,36.43 42.22,36.05 42.22,35.59 v1(42.22,35.59)
  BOTTOM w0.089: JX4.41 85.19,34.57 84.89,34.27 84.63,34.27 v1(84.38,34.53)
IO_L09_35_TX_FRAME_N: length 31.6
  TOP w0.089: U1.J15 v1(39.22,28.59) ; v6(62.8,31.29) U17.H9
  L6_SIG w0.089: v1(39.22,28.59) 38.81,28.61 38.74,28.53 38.74,28.43 38.81,28.35 38.81,27.5 39.05,27.25 39.35,27.25 39.63,27.52 39.63,27.83 39.97,28.18 40.28,28.18 40.55,28.45 40.55,28.9 40.56,28.92 40.57,28.93 40.57,29.72 40.62,29.78 40.62,29.83 40.97,30.18 41.02,30.18 41.09,30.25 42.35,30.25 42.62,30.52 42.63,30.62 42.85,30.84 43.49,30.84 43.74,30.59 43.74,30.51 43.99,30.25 51.55,30.25 51.93,30.63 53.71,30.63 53.96,30.38 54.53,30.38 54.57,30.33 55.15,30.33 55.45,30.63 57.65,30.63 58.49,31.48 59.43,31.48 59.82,31.09 59.82,31 60.04,30.79 62.87,30.79 63.04,30.97 63.04,31.13 62.96,31.22 62.87,31.22 v6(62.8,31.29)
IO_L09_35_TX_FRAME_P: length 31.3
  TOP w0.089: U1.K15 v1(38.22,28.59) ; v6(62.8,30.49) U17.G9
  L6_SIG w0.089: v6(62.8,30.49) 62.79,30.49 62.79,30.33 62.54,30.08 62.28,30.08 62.17,30.19 60.27,30.19 59.57,30.9 59.57,30.98 59.33,31.22 58.6,31.22 57.75,30.38 55.55,30.38 55.25,30.08 54.46,30.08 54.42,30.12 53.86,30.12 53.6,30.38 52.04,30.38 51.66,30 43.89,30 43.49,30.4 43.49,30.48 43.38,30.59 42.96,30.59 42.88,30.51 42.88,30.45 42.85,30.4 42.85,30.4 42.84,30.39 42.82,30.36 42.46,30 41.2,30 41.13,29.93 41.08,29.93 40.88,29.73 40.88,29.68 40.82,29.62 40.82,28.92 40.81,28.34 40.39,27.92 40.08,27.92 39.88,27.73 39.88,27.42 39.46,27 38.95,27 38.55,27.39 38.55,28.25 38.24,28.59 v1(38.22,28.59)
IO_L10_12_JX3_N: length 72.5
  TOP w0.089: U1.AF13 v1(21.22,31.59)
  L15_SIG w0.089: v1(14.66,43.8) 14.47,43.61 14.34,43.61 14.28,43.67 14.28,44.05 14.4,44.18 14.66,44.18 14.91,44.43 14.91,44.69 14.78,44.81 14.78,45.02 14.91,45.15 14.91,45.6 14.5,46 14.24,46 13.91,46.34 13.15,46.34 12.63,46.87 12.63,49.28 12.39,49.51 9.73,49.51 9.2,50.04 9.2,50.3 8.96,50.53 7.78,50.53 7.55,50.3 7.55,46.31 7.78,46.08 11.33,46.08 11.86,45.55 11.86,40.39 11.33,39.86 10.19,39.86 10.09,39.75 9.58,39.75 9.47,39.86 7.9,39.86 7.67,39.63 7.67,34 7.9,33.76 13.01,33.76 13.39,33.38 13.39,32.75 13.01,32.37 9.8,32.37 9.72,32.45 9.44,32.45 9.36,32.37 7.65,32.37 7.42,32.13 7.42,30.97 8.31,30.08 14.49,30.08 14.66,30.25 21.35,30.25 21.59,30.49 21.59,31.32 21.82,31.55 21.82,31.93 21.69,32.06 21.46,32.06 21.26,31.86 21.26,31.63 v1(21.22,31.59)
  BOTTOM w0.089: v1(14.66,43.8) 14.53,43.8 13.9,43.16 13.51,43.16 13.3,43.37 JX3.82
IO_L10_12_JX3_P: length 72.5
  TOP w0.089: U1.AE13 v1(22.22,31.59)
  L15_SIG w0.089: v1(14.7,43.25) 14.77,43.33 14.78,43.33 14.98,43.52 14.98,43.65 14.99,43.66 14.99,43.82 15.04,43.87 15.04,44.2 15.17,44.33 15.17,45.7 14.61,46.26 14.35,46.26 14.01,46.59 13.26,46.59 12.88,46.97 12.88,49.38 12.5,49.77 9.83,49.77 9.45,50.15 9.45,50.4 9.07,50.78 7.67,50.78 7.29,50.4 7.29,46.21 7.67,45.83 11.23,45.83 11.61,45.45 11.61,40.49 11.23,40.11 10.09,40.11 9.98,40.01 9.68,40.01 9.57,40.11 7.8,40.11 7.42,39.73 7.42,33.89 7.8,33.51 12.9,33.51 13.13,33.28 13.13,32.85 12.9,32.62 9.9,32.62 9.82,32.7 9.33,32.7 9.25,32.62 7.55,32.62 7.16,32.24 7.16,30.86 8.2,29.83 14.59,29.83 14.76,30 21.46,30 21.84,30.38 21.84,31.22 22.01,31.39 v1(22.22,31.59)
  BOTTOM w0.089: v1(14.7,43.25) 14.66,43.25 14.62,43.29 14.33,43.29 13.95,42.91 13.64,42.91 13.31,42.57 JX3.80
IO_L10_13_JX2_N: length 74.3
  TOP w0.089: U1.AA23 v1(26.22,20.59)
  L6_SIG w0.089: v1(42.98,8.74) 42.72,8.49 42.72,8.36 42.85,8.24 43.23,8.24 43.36,8.11 43.36,7.86 43.23,7.73 42.72,7.73 42.6,7.6 42.6,3.26 43,2.86 47.03,2.86 47.12,2.78 52.56,2.78 52.91,3.12 52.91,3.16 53.16,3.41 56.08,3.41 56.72,4.05 57.86,4.05 58.47,4.66 58.47,8.47 58.6,8.6 58.6,10.14 58.22,10.52 57.48,10.52 56.95,11.05 56.95,13.59 55.57,14.97 52.14,14.97 51.89,15.22 50.88,15.22 50.63,14.97 47.66,14.97 47.02,14.33 40.38,14.33 40.05,14 39.56,14 39.22,14.33 38.85,14.33 38.77,14.25 37.4,14.25 37.32,14.33 36.14,14.33 34.62,15.86 29.16,15.86 28.55,16.46 28.55,20.73 28.32,20.96 26.49,20.96 26.39,20.86 26.39,20.77 v1(26.22,20.59)
  BOTTOM w0.089: v1(42.98,8.74) 42.81,8.58 42.81,7.62 43.13,7.3 JX2.32
IO_L10_13_JX2_P: length 74.4
  TOP w0.089: U1.AA22 v1(26.22,21.59)
  L6_SIG w0.089: v1(26.22,21.59) 26.59,21.22 28.42,21.22 28.81,20.83 28.81,16.57 29.26,16.11 34.72,16.11 36.25,14.59 37.42,14.59 37.5,14.5 38.66,14.5 38.74,14.59 39.33,14.59 39.66,14.25 39.94,14.25 40.28,14.59 46.92,14.59 47.55,15.22 50.52,15.22 50.78,15.48 52,15.48 52.25,15.22 55.68,15.22 57.2,13.7 57.2,11.16 57.58,10.78 58.32,10.78 58.85,10.25 58.85,8.49 58.73,8.36 58.73,4.55 57.96,3.79 56.82,3.79 56.19,3.16 53.27,3.16 53.16,3.05 53.16,3 53.14,2.98 53.13,2.98 52.66,2.52 47.01,2.52 46.93,2.6 42.9,2.6 42.34,3.16 v1(42.34,8.74)
  BOTTOM w0.089: JX2.30 42.33,7.33 42.6,7.6 42.6,8.49 v1(42.34,8.74)
IO_L10_33_JX1_N: length 72.2
  TOP w0.089: U1.G1 v1(41.22,43.59)
  L15_SIG w0.089: v1(41.22,43.59) 40.87,43.24 40.87,43.12 41.06,42.92 41.35,42.92 41.58,42.7 41.58,42.53 41.86,42.25 42.35,42.25 42.55,42.45 42.55,42.46 42.6,42.5 42.6,43.82 41.71,44.71 41.71,46.57 42.24,47.1 45.67,47.1 45.9,47.33 45.9,48.14 45.67,48.37 44.45,48.37 44.24,48.16 43.75,48.16 43.4,48.5 43.4,48.99 43.61,49.2 43.61,50.38 44.02,50.78 53.92,50.78 54.15,51.01 54.15,56.12 54.54,56.5 62.28,56.5 62.54,56.75 62.54,58.27 62.79,58.53 64.57,58.53 64.95,58.15 64.95,56.88 65.33,56.5 66.47,56.5 66.85,56.88 66.85,58.27 67.24,58.66 69.01,58.66 69.39,58.27 69.39,56.88 69.78,56.5 70.82,56.5 71.17,56.14 71.17,55.64 70.82,55.29 60.95,55.29 60.63,54.97 60.63,54.08 v1(60.76,53.96)
  BOTTOM w0.089: JX1.75 60.73,54.6 60.48,54.36 60.48,54.23 v1(60.76,53.96)
IO_L10_33_JX1_P: length 72.2
  TOP w0.089: U1.H2 v1(40.22,42.59)
  L15_SIG w0.089: v1(40.22,42.59) 40.31,42.68 40.31,42.91 40.39,42.98 40.64,42.98 40.88,42.75 40.88,42.45 41.08,42.25 41.5,42.25 41.75,42 42.46,42 42.81,42.34 42.81,42.35 42.85,42.4 42.85,43.93 41.97,44.81 41.97,46.46 42.35,46.84 45.77,46.84 46.15,47.23 46.15,48.24 45.77,48.62 44.34,48.62 44.13,48.41 43.85,48.41 43.66,48.61 43.66,48.89 43.87,49.1 43.87,50.27 44.12,50.53 54.03,50.53 54.41,50.91 54.41,56.01 54.64,56.24 62.39,56.24 62.79,56.65 62.79,58.17 62.9,58.27 64.46,58.27 64.7,58.04 64.7,56.77 65.22,56.24 66.58,56.24 67.11,56.77 67.11,58.17 67.34,58.4 68.91,58.4 69.14,58.17 69.14,56.77 69.67,56.24 70.71,56.24 70.92,56.04 70.92,55.75 70.71,55.54 61.05,55.54 60.84,55.54 60.38,55.08 60.38,54.21 v1(60.12,53.96)
  BOTTOM w0.089: JX1.73 59.93,54.66 60.25,54.34 60.25,54.08 v1(60.12,53.96)
IO_L10_34_JX4_N: length 73.5
  TOP w0.089: U1.D5 v1(44.22,39.59)
  L17_SIG w0.089: v1(80.19,33.89) 79.38,33.89 79.25,33.76 79.25,33.46 79.33,33.38 81.08,33.38 81.21,33.26 81.21,23.2 80.97,22.97 78.82,22.97 78.59,23.2 78.59,33.56 78.21,33.94 77.7,33.94 76.5,35.14 75.96,35.14 72.89,38.21 67.59,38.21 67.21,38.59 67.21,39.73 66.83,40.11 66.09,40.11 65.71,40.49 65.71,43.39 65.18,43.92 63.57,43.92 63.04,43.39 63.04,42.17 63.13,42.09 63.13,41.63 62.66,41.16 62.66,40.49 62.28,40.11 58.85,40.11 58.34,39.61 47.83,39.61 47.44,39.22 44.5,39.22 44.22,39.51 v1(44.22,39.59)
  BOTTOM w0.089: JX4.44 80.79,33.77 80.49,34.07 80.37,34.07 v1(80.19,33.89)
IO_L10_34_JX4_P: length 73.6
  TOP w0.089: U1.E6 v1(43.22,38.59)
  L17_SIG w0.089: v1(80.19,34.53) 80.7,34.02 80.7,33.76 80.82,33.64 81.18,33.64 81.46,33.36 81.46,23.1 81.08,22.71 78.72,22.71 78.34,23.1 78.34,33.46 78.1,33.69 77.6,33.69 76.4,34.89 75.85,34.89 72.79,37.95 67.49,37.95 66.96,38.48 66.96,39.63 66.73,39.86 65.99,39.86 65.46,40.39 65.46,43.29 65.08,43.67 63.68,43.67 63.3,43.29 63.3,42.27 63.38,42.19 63.38,41.52 62.92,41.06 62.92,40.39 62.39,39.86 58.96,39.86 58.45,39.35 47.93,39.35 47.55,38.97 43.81,38.97 43.55,38.71 43.34,38.71 v1(43.22,38.59)
  BOTTOM w0.089: JX4.42 80.74,34.57 80.51,34.33 80.38,34.33 v1(80.19,34.53)
IO_L10_35_EN_AGC: length 28.9
  TOP w0.14: U1.G16 v1(41.22,27.59) ; v6(66.8,30.49) U17.G5
  L6_SIG w0.095: v6(66.8,30.49) 66.76,30.49 65.46,29.19 64.44,29.19 63.81,28.56 59.23,28.56 58.96,28.29 58.96,28.28 58.52,27.84 56.95,27.84 56.83,27.95 56.83,27.95 56.63,28.15 56.63,28.18 56.53,28.27 56.53,28.39 56.33,28.59 56.05,28.59 56.02,28.56 55.57,28.56 55.53,28.59 55.25,28.59 55.05,28.39 55.05,28.34 54.75,28.04 54.75,28.03 54.55,27.84 54.27,27.84 54.18,27.93 44.07,27.93 44.07,27.92 43.36,27.92 43.36,27.93 41.56,27.93 v1(41.22,27.59)
IO_L10_35_SYNC_IN: length 40
  TOP w0.14: U1.G15 v1(41.22,28.59) ; v6(66.8,31.29) U17.H5
  L14_SIG w0.095: v6(66.8,31.29) 67.11,31.6 67.11,32.1 67.4,32.39 67.72,32.39 67.9,32.22 67.9,32.21 68.1,32.01 68.1,31.97 68.27,31.79 68.32,31.79 68.51,31.59 68.52,31.59 68.7,31.42 68.7,31.17 68.63,31.1 68.63,30.68 68.7,30.62 68.7,30.37 68.63,30.3 68.63,29.08 68.7,29.02 68.7,28.77 68.63,28.7 68.63,28.28 68.7,28.22 68.7,27.97 68.63,27.9 68.63,27.48 68.7,27.42 68.7,27.17 68.52,26.99 68.46,26.99 68.38,26.91 65.97,26.91 65.88,26.99 65.87,26.99 65.7,27.17 65.7,27.18 65.5,27.37 65.5,27.42 65.32,27.59 65.07,27.59 65.02,27.54 64.58,27.54 64.52,27.59 64.27,27.59 64.22,27.54 63.78,27.54 63.72,27.59 63.47,27.59 63.42,27.54 62.98,27.54 62.92,27.59 62.67,27.59 62.62,27.54 62.18,27.54 62.12,27.59 61.87,27.59 61.82,27.54 61.38,27.54 61.32,27.59 59.94,27.59 59.17,28.37 58.64,28.37 58.61,28.34 58.33,28.34 58.13,28.54 58.13,29.28 57.17,30.24 55.84,30.24 55.82,30.26 55.54,30.26 55.34,30.06 55.34,29.87 54.15,28.68 49.2,28.68 48.82,29.06 41.71,29.06 41.23,28.59 v1(41.22,28.59)
  BOTTOM w0.14: R111.2 66.79,31.3 v6(66.8,31.29)
IO_L11_35_ENABLE: length 28
  TOP w0.14: v6(66,30.49) U17.G6 ; U1.G14 v1(41.22,29.59)
  L6_SIG w0.095: v6(66,30.49) 65.36,30.49 64.44,29.57 64.06,29.57 63.68,29.19 63.47,29.19 63.47,29.19 62.93,29.19 62.92,29.19 62.67,29.19 62.67,29.19 62.13,29.19 62.12,29.19 61.87,29.19 61.87,29.19 61.33,29.19 61.32,29.19 61.07,29.19 61.07,29.19 60.53,29.19 60.52,29.19 60.27,29.19 60.27,29.19 57.96,29.19 57.58,28.81 56.43,28.81 56.43,28.81 55.96,28.81 55.96,28.81 55.63,28.81 55.62,28.81 55.16,28.81 55.16,28.81 51.57,28.81 51.53,28.78 51.25,28.78 51.22,28.81 50.77,28.81 50.73,28.78 50.45,28.78 50.42,28.81 48.57,28.81 47.93,28.18 42.15,28.18 41.88,28.45 41.88,28.52 41.71,28.68 41.71,29.1 v1(41.22,29.59)
IO_L11_35_TXNRX: length 28.3
  TOP w0.14: U1.F14 v1(42.22,29.59) ; v6(67.6,31.29) U17.H4
  L6_SIG w0.095: v1(42.22,29.59) 42.61,29.19 49.39,29.19 49.65,29.45 51.53,29.45 51.8,29.19 54.93,29.19 55.25,29.52 56.33,29.52 56.58,29.27 56.94,29.27 57.32,29.65 57.52,29.65 57.52,29.65 57.6,29.65 57.8,29.45 63.43,29.45 63.8,29.83 64.31,29.83 65.33,30.84 67.11,30.84 67.56,31.29 v6(67.6,31.29)
IO_L11_SRCC_12_JX3_N: length 72.1
  TOP w0.089: U1.AD11 v1(23.22,33.59)
  L15_SIG w0.089: v1(23.22,33.59) 23.47,33.59 23.56,33.49 23.56,33.12 23.37,32.93 23.08,32.93 22.88,32.73 22.88,32.32 22.55,32 22.55,31.45 22.53,31.43 22.53,29.75 22.55,29.73 22.55,29.45 22.35,29.25 22.21,29.25 22.15,29.19 20.37,29.19 19.74,28.56 18.09,28.56 17.71,28.94 17.71,29.19 17.32,29.57 15.17,29.57 14.78,29.19 10.72,29.19 10.34,28.81 10.34,28.05 9.45,27.16 8.05,27.16 7.29,27.92 7.29,28.79 6.25,29.83 5.51,29.83 5.26,30.08 5.26,32.11 5.01,32.37 1.38,32.37 1.2,32.55 1.2,32.82 1.38,33 5.39,33 5.64,33.26 5.64,33.89 5.39,34.14 1.43,34.14 1.2,34.38 1.2,35.56 1.43,35.8 6.58,35.8 6.91,36.13 6.91,36.6 6.58,36.94 2.06,36.94 1.83,37.17 1.83,37.85 2.06,38.08 4.6,38.08 5.13,38.61 5.13,39.35 6.66,40.88 6.66,43.29 7.16,43.8 7.16,45.19 6.66,45.7 6.66,45.83 v1(6.28,46.21)
  BOTTOM w0.089: JX3.87 7.36,45.77 7.04,45.45 6.78,45.45 6.28,45.96 v1(6.28,46.21)
IO_L11_SRCC_12_JX3_P: length 72.1
  TOP w0.089: U1.AC12 v1(24.22,32.59)
  L15_SIG w0.089: v1(6.02,45.7) 6.2,45.52 6.48,45.52 6.91,45.09 6.91,43.9 6.4,43.39 6.4,40.98 4.88,39.46 4.88,38.72 4.5,38.34 1.96,38.34 1.58,37.95 1.58,37.07 1.96,36.68 6.47,36.68 6.66,36.5 6.66,36.24 6.47,36.05 1.32,36.05 0.94,35.67 0.94,34.27 1.32,33.89 5.28,33.89 5.39,33.79 5.39,33.36 5.28,33.26 1.28,33.26 0.94,32.92 0.94,32.45 1.28,32.11 4.9,32.11 5.01,32.01 5.01,29.98 5.41,29.57 6.15,29.57 7.04,28.68 7.04,27.82 7.95,26.91 9.56,26.91 10.59,27.94 10.59,28.71 10.83,28.94 14.89,28.94 15.27,29.32 17.22,29.32 17.45,29.09 17.45,28.83 17.98,28.3 19.84,28.3 20.48,28.94 22.26,28.94 22.32,29 22.46,29 22.81,29.34 22.81,29.83 22.79,29.85 22.79,31.32 22.81,31.34 22.81,31.89 23.17,32.25 23.35,32.25 23.55,32.45 23.55,32.75 23.74,32.94 23.87,32.94 v1(24.22,32.59)
  BOTTOM w0.089: JX3.85 7.3,44.97 7.04,45.23 6.69,45.23 6.22,45.7 v1(6.02,45.7)
IO_L11_SRCC_13_JX2_N: length 74.3
  TOP w0.089: U1.AD24 v1(23.22,19.59)
  L14_SIG w0.089: v1(45.39,12.43) 45.26,12.3 45.26,10.75 45.5,10.52 46.68,10.52 47.44,11.28 47.91,11.28 48.44,10.75 48.44,9.99 48.67,9.76 49.1,9.76 49.33,9.99 49.33,10.75 49.86,11.28 50.73,11.28 51.11,10.9 51.11,7.75 50.58,7.22 41.96,7.22 40.69,8.49 40.33,8.49 39.93,8.89 39.93,9.66 39.57,10.01 38.38,10.01 37.62,9.25 34.85,9.25 34.34,9.76 34.34,10.18 34.69,10.52 37.26,10.52 37.9,11.16 40.18,11.16 40.82,10.52 43.89,10.52 44.12,10.75 44.12,11.31 43.89,11.54 39.06,11.54 38.53,12.07 38.53,14.08 38.41,14.21 31.42,14.21 30.79,14.84 25.85,14.84 25.07,15.62 25.07,16.49 24.55,17.01 24.55,19.73 24.35,19.93 24.01,19.93 23.94,19.96 23.59,19.96 v1(23.22,19.59)
  BOTTOM w0.089: JX2.37 45.53,11.78 45.26,12.05 45.26,12.3 v1(45.39,12.43)
IO_L11_SRCC_13_JX2_P: length 74.3
  TOP w0.089: U1.AD23 v1(23.22,20.59)
  L14_SIG w0.089: v1(23.22,20.59) 23.17,20.54 23.17,20.26 23.28,20.14 23.41,20.14 23.48,20.22 23.55,20.22 23.63,20.3 23.8,20.3 23.89,20.22 24.01,20.22 24.08,20.18 24.46,20.18 24.81,19.83 24.81,17.12 25.33,16.6 25.33,15.73 25.96,15.09 30.89,15.09 31.53,14.46 38.51,14.46 38.79,14.18 38.79,12.17 39.17,11.79 43.99,11.79 44.38,11.41 44.38,10.86 44.38,10.81 44.38,10.81 44.38,10.65 43.99,10.27 40.71,10.27 40.08,10.9 38,10.9 37.37,10.27 34.79,10.27 34.6,10.07 34.6,9.87 34.96,9.51 37.52,9.51 38.28,10.27 39.68,10.27 40.18,9.76 40.18,9 40.44,8.74 40.8,8.74 42.07,7.47 50.47,7.47 50.85,7.86 50.85,10.8 50.62,11.03 49.96,11.03 49.58,10.65 49.58,9.89 49.2,9.51 48.57,9.51 48.19,9.89 48.19,10.65 47.8,11.03 47.55,11.03 46.79,10.27 45.39,10.27 45.01,10.65 45.01,12.3 v1(44.88,12.43)
  BOTTOM w0.089: JX2.35 44.73,11.76 45.01,12.05 45.01,12.3 v1(44.88,12.43)
IO_L11_SRCC_33_JX1_N: length 72.2
  TOP w0.089: U1.K3 v1(38.22,41.59)
  L4_SIG w0.089: v1(38.22,41.59) 37.84,41.96 37.84,43.74 38.28,44.18 46.03,44.18 46.53,44.69 46.53,45.89 48.89,48.24 54.01,48.24 54.13,48.37 54.94,48.37 55.06,48.24 58.09,48.24 58.49,47.84 58.5,47.84 58.71,47.63 58.71,47.33 58.47,47.09 58.47,46.57 59,46.04 65.21,46.04 65.25,46 65.79,46 65.83,46.04 76.48,46.04 77.01,46.57 77.01,48.6 76.48,49.13 74.09,49.13 73.71,49.51 73.71,49.64 73.33,50.02 72.32,50.02 71.77,49.47 71.77,49.4 71.1,48.73 71.1,47.84 70.87,47.61 68.38,47.61 68,47.99 68,48.24 67.62,48.62 65.99,48.62 65.61,48.24 65.61,47.86 65.22,47.48 65.05,47.48 64.29,48.24 60.85,48.24 60.48,48.61 60.48,49.36 v1(60.63,49.51)
  BOTTOM w0.089: v1(60.63,49.51) 60.38,49.76 60.38,49.89 60.73,50.24 JX1.76
IO_L11_SRCC_33_JX1_P: length 72.1
  TOP w0.089: U1.L3 v1(37.22,41.59)
  L4_SIG w0.089: v1(60.02,49.51) 60.22,49.31 60.22,48.51 60.74,47.99 64.19,47.99 64.95,47.23 65.33,47.23 65.86,47.76 65.86,48.14 66.09,48.37 67.51,48.37 67.74,48.14 67.74,47.88 68.27,47.35 70.97,47.35 71.35,47.73 71.35,48.62 72.02,49.29 72.02,49.37 72.42,49.77 73.23,49.77 73.46,49.53 73.46,49.41 73.99,48.88 76.38,48.88 76.76,48.5 76.76,46.67 76.38,46.29 65.72,46.29 65.69,46.25 65.35,46.25 65.32,46.29 59.11,46.29 58.73,46.67 58.73,46.99 58.96,47.22 58.96,47.73 58.6,48.1 58.6,48.1 58.2,48.5 55.17,48.5 55.04,48.62 54.03,48.62 53.9,48.5 48.78,48.5 46.28,45.99 46.28,44.79 45.92,44.43 38.17,44.43 37.59,43.85 37.59,41.96 v1(37.22,41.59)
  BOTTOM w0.089: v1(60.02,49.51) 60.16,49.65 60.16,49.89 59.93,50.13 JX1.74
IO_L11_SRCC_34_JX4_N: length 72.9
  TOP w0.089: U1.E7 v1(43.22,37.59)
  L14_SIG w0.089: v1(43.22,37.59) 42.9,37.27 42.9,37.21 42.93,37.18 47.3,37.18 49.6,39.48 61.14,39.48 61.39,39.73 62.26,39.73 62.51,39.48 64.04,39.48 64.27,39.71 64.27,40.45 64.57,40.75 64.57,41.64 64.95,42.02 67.74,42.02 68.12,42.4 68.12,42.65 68.51,43.03 69.65,43.03 70.03,42.65 70.03,42.4 70.41,42.02 73.46,42.02 73.84,42.4 73.84,44.3 74.22,44.69 80.03,44.69 80.08,44.63 80.36,44.63 80.41,44.69 81.31,44.69 81.84,44.16 81.84,41.43 82.07,41.19 83.24,41.19 83.62,41.58 83.62,43.92 84,44.3 86.41,44.3 86.79,43.92 86.79,33.13 86.03,32.37 84.51,32.37 v1(84.38,32.24)
  BOTTOM w0.089: JX4.47 85.12,32.17 84.89,32.4 84.55,32.4 v1(84.38,32.24)
IO_L11_SRCC_34_JX4_P: length 72.9
  TOP w0.089: U1.F8 v1(42.22,36.59)
  L14_SIG w0.089: v1(42.22,36.59) 42.56,36.94 42.75,36.94 42.76,36.92 47.41,36.92 49.71,39.22 61.24,39.22 61.5,39.48 62.16,39.48 62.41,39.22 64.14,39.22 64.52,39.61 64.52,40.34 64.82,40.64 64.82,41.53 65.05,41.76 67.85,41.76 68.38,42.29 68.38,42.55 68.61,42.78 69.54,42.78 69.78,42.55 69.78,42.29 70.3,41.76 73.56,41.76 74.09,42.29 74.09,44.2 74.33,44.43 79.93,44.43 79.98,44.38 80.47,44.38 80.52,44.43 81.21,44.43 81.59,44.05 81.59,41.32 81.97,40.94 83.34,40.94 83.87,41.47 83.87,43.82 84.1,44.05 86.31,44.05 86.54,43.82 86.54,33.23 85.93,32.62 85.52,32.62 85.4,32.75 85.4,32.87 85.14,33.13 85.02,33.13 84.89,33 84.89,32.87 84.63,32.62 84.51,32.62 v1(84.38,32.75)
  BOTTOM w0.089: v1(84.38,32.75) 84.51,32.62 84.89,32.62 85.24,32.97 JX4.45
IO_L12_MRCC_12_JX3_N: length 74.3
  TOP w0.089: U1.AD13 v1(23.22,31.59)
  L7_SIG w0.089: v1(14.02,45.7) 14.02,45.54 13.8,45.32 13.64,45.32 13.51,45.45 13.51,45.96 13.39,46.08 13.26,46.08 13.13,45.96 13.13,45.57 12.88,45.32 12.73,45.32 12.5,45.55 12.5,45.96 13.01,46.46 13.78,46.46 14.24,46 14.74,46 14.86,45.88 15.29,45.45 16.29,45.45 16.82,45.98 16.82,51.27 16.29,51.8 12.48,51.8 12.24,52.03 12.24,53.93 11.71,54.46 10.95,54.46 10.72,54.7 10.72,57.37 11.1,57.75 16.53,57.75 16.55,57.77 19.86,57.77 20.25,57.39 20.25,55.88 20.77,55.35 24.84,55.35 25.07,55.12 25.07,50.89 24.84,50.65 20.77,50.65 20.25,50.12 20.25,46.36 20.77,45.83 22.15,45.83 23.59,44.39 23.59,31.96 v1(23.22,31.59)
  BOTTOM w0.089: JX3.88 13.41,45.77 13.64,45.54 13.86,45.54 v1(14.02,45.7)
